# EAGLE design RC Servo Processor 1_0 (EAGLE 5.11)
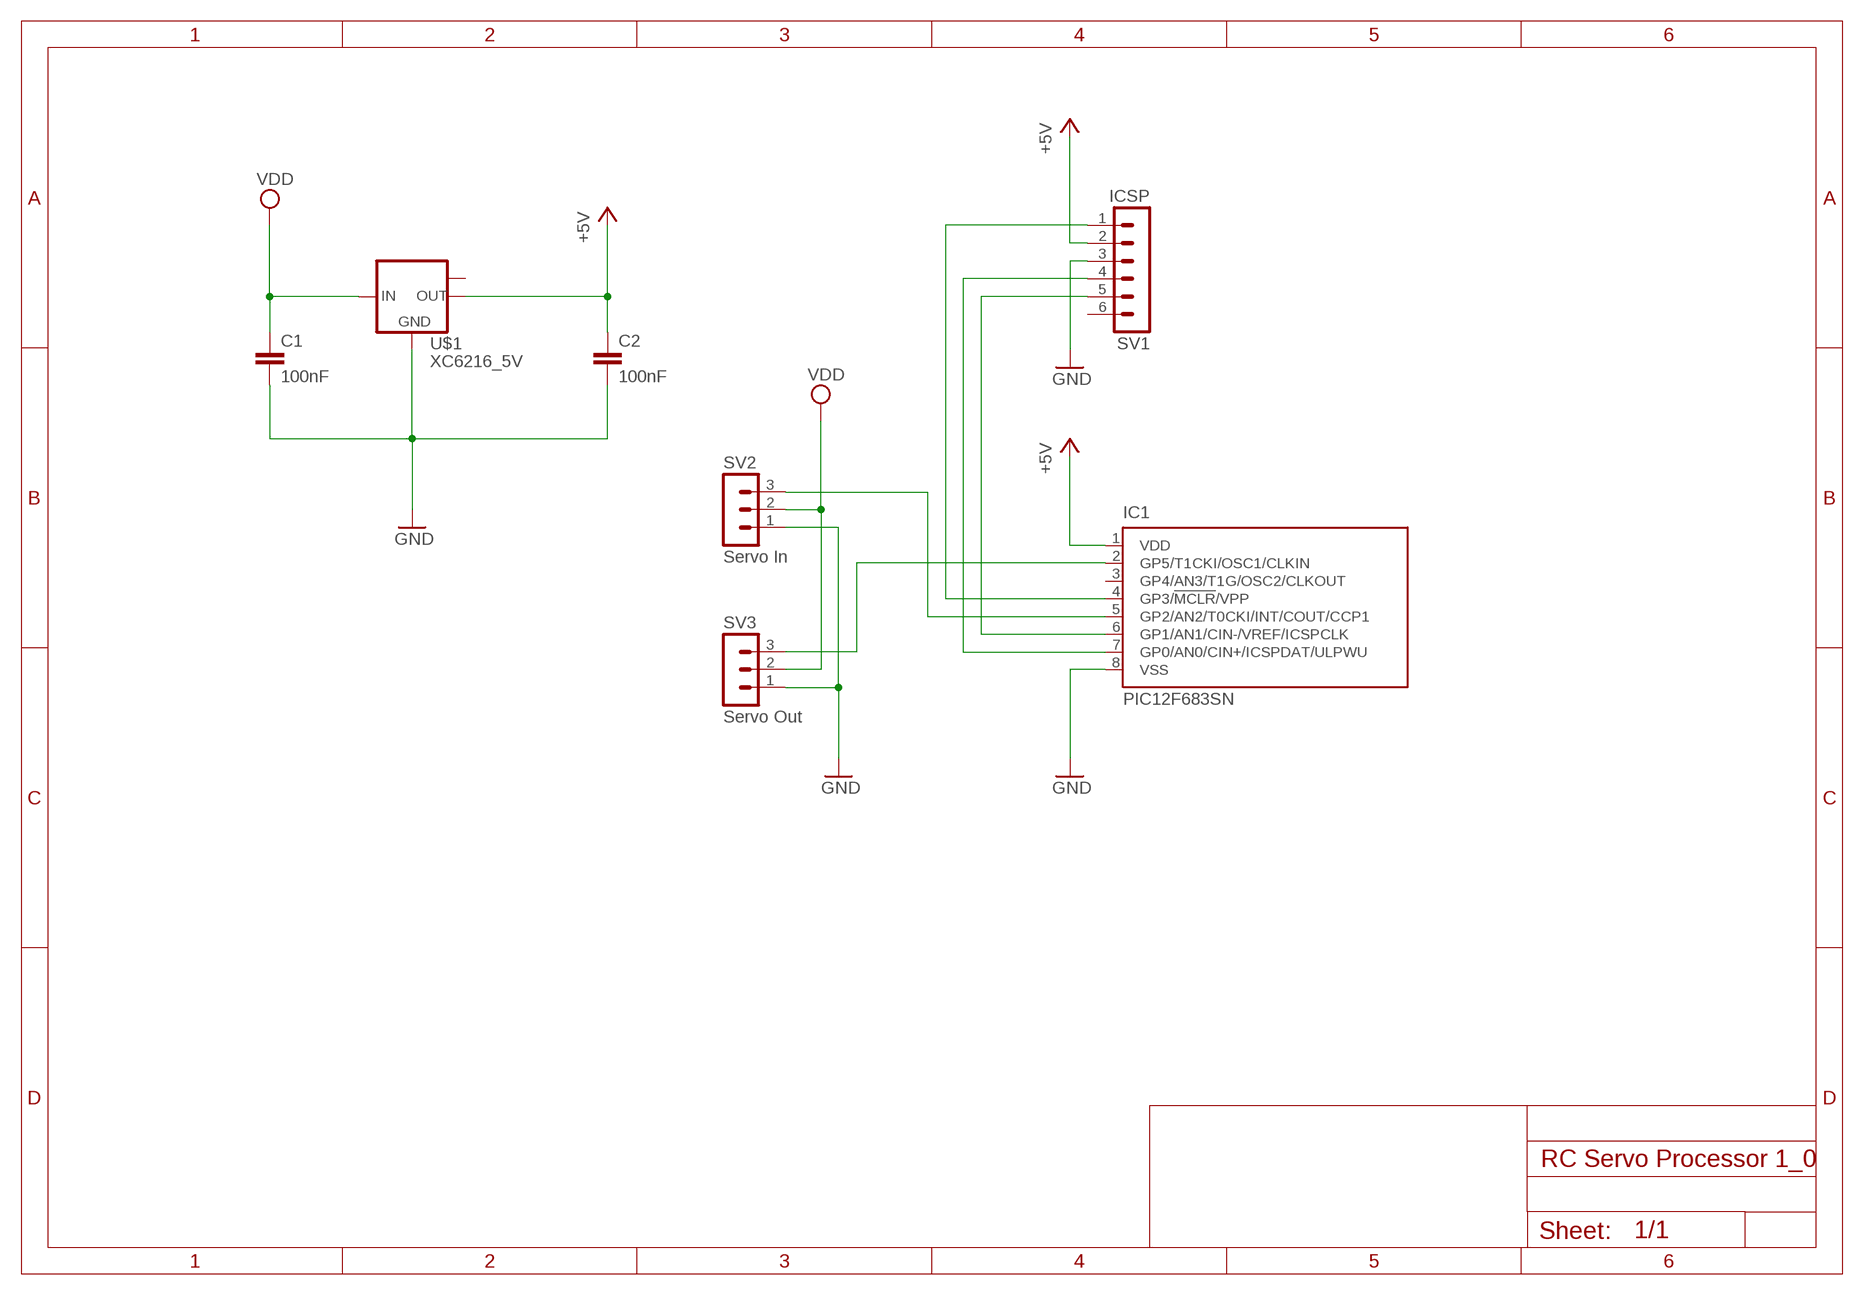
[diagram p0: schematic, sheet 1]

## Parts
C1  100nF  C-EUC0805K  [C0805K]
C2  100nF  C-EUC0805K  [C0805K]
IC1  PIC12F683SN  [SO-08]
SV1  ICSP  MA06-1  [MA06-1]
SV2  Servo In  MA03-1  [MA03-1]
SV3  Servo Out  MA03-1  [MA03-1]
U$1  XC6216_5V  [SOT223]

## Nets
+5V: C2.1 IC1.1(VDD) SV1.2 U$1.1(OUT)
GND: C1.2 C2.2 IC1.8(VSS) SV1.3 SV2.1 SV3.1 U$1.2(GND)
N$1: IC1.4(GP3/!MCLR!/VPP) SV1.1
N$2: IC1.5(GP2/AN2/T0CKI/INT/COUT/CCP1) SV2.3
N$3: IC1.2(GP5/T1CKI/OSC1/CLKIN) SV3.3
N$4: IC1.7(GP0/AN0/CIN+/ICSPDAT/ULPWU) SV1.4
N$5: IC1.6(GP1/AN1/CIN-/VREF/ICSPCLK) SV1.5
VDD: C1.1 SV2.2 SV3.2 U$1.3(IN)
Unconnected: IC1.3(GP4/AN3/T1G/OSC2/CLKOUT) SV1.6 U$1.TAB(OUT1)

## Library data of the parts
C1 C2 = rcl:C-EU: CAPACITOR, European symbol
IC1 = microchip:PIC12F683: 8-Pin Flash-Based, 8-Bit CMOS Microcontrollers with nanoWatt Technology Source: http://ww1.microchip.com/downloads/en/DeviceDoc/41211D_.pdf; MF: MICROCHIP; MPN: PIC12F683-I/SN; OC_FARNELL: 9759042; OC_NEWARK: 61K3434
SV1 = con-lstb:MA06-1: PIN HEADER; OC_FARNELL: unknown; OC_NEWARK: unknown
SV2 SV3 = con-lstb:MA03-1: PIN HEADER; OC_FARNELL: unknown; OC_NEWARK: unknown
U$1 = simonslbr:XC6216_5V: XC6216 LDO 5V Regulator

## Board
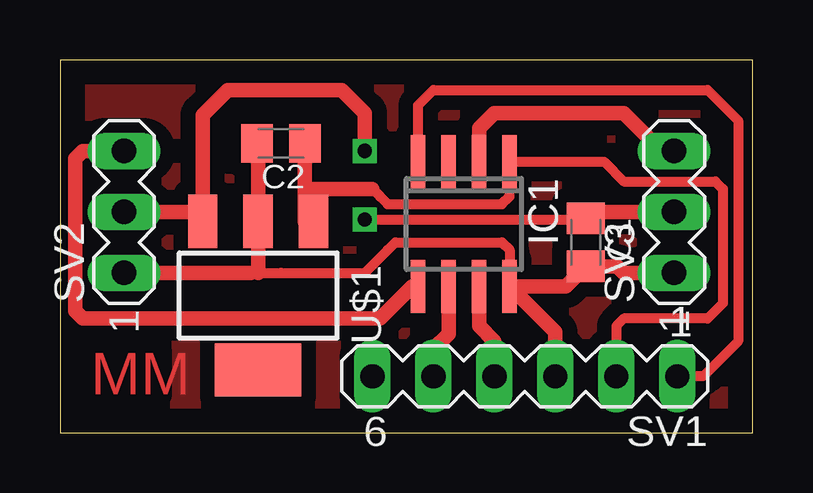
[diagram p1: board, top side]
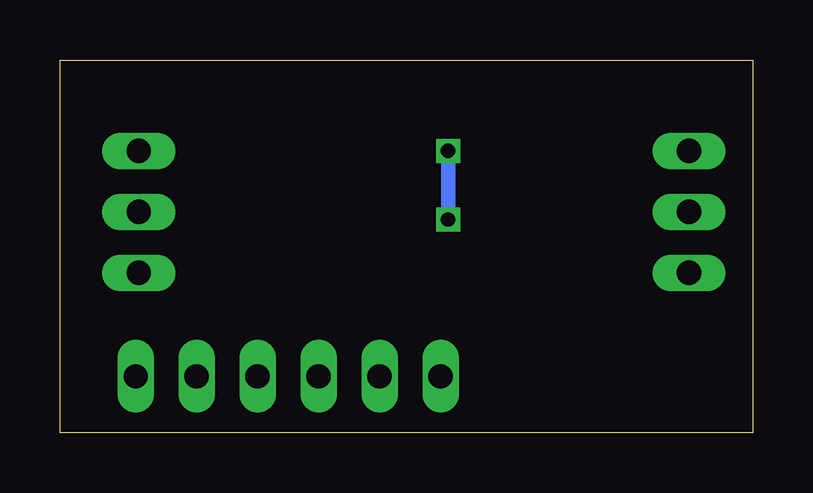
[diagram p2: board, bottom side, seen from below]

Size 28.87 x 15.54 mm. Coordinates in mm from the lower left corner, seen from the top.
Outline: 0,0 28.87,0 28.87,15.54 0,15.54 0,0
Copper layers (1*16): Top 0.035mm / dielectric 1.5mm / Bottom 0.035mm
Design rules "default": minimum track width 10mil, minimum drill 24mil, track to track 8mil, track to pad 8mil, pad to pad 8mil, via to via 8mil, smd to smd 8mil, copper to edge 40mil, drill to drill 8mil, minimum pad ring 10mil, minimum via ring 8mil, stop-mask expansion 4mil, vias tented up to drill 0mil, thermal gap 10mil

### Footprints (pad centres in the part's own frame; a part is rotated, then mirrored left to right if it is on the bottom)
C0805K = smd 1.3 x 1.6: 1 -1,0; 2 1,0
SO-08 = smd 0.6 x 2.2: 1 -1.905,-2.6; 2 -0.635,-2.6; 3 0.635,-2.6; 4 1.905,-2.6; 5 1.905,2.6; 6 0.635,2.6; 7 -0.635,2.6; 8 -1.905,2.6
MA06-1 = drill 1.016 long: 1 -6.35,0; 2 -3.81,0; 3 -1.27,0; 4 1.27,0; 5 3.81,0; 6 6.35,0
MA03-1 = drill 1.016 long: 1 -2.54,0; 2 0,0; 3 2.54,0
SOT223 = smd 1.219 x 2.235: 1 -2.311,-3.099; 2 0,-3.099; 3 2.311,-3.099 | smd 3.6 x 2.2: TAB 0,3.099

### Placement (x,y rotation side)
C1  21.91,7.94 270 top
C2  9.21,12.06 180 top
IC1  16.83,8.7 180 top
SV1  19.37,2.35 180 top
SV2  2.67,9.21 90 top
SV3  25.59,9.21 90 top
U$1  8.26,5.71 180 top

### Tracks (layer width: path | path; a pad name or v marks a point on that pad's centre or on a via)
+5V
  Top 0.406: SV1.2 23.18,4.45 23.5,4.76 26.99,4.76 27.62,5.4 27.62,10.16 27.3,10.48 23.5,10.48 22.67,11.3 IC1.1 18.73,9.84 18.41,9.53 13.65,9.53 13.34,9.84 13.02,10.16
  Top 0.61: C2.1 10.21,8.81 U$1.1 10.57,10.16 13.02,10.16
GND
  Top 0.406: IC1.8 18.73,7.62 18.41,7.94 13.97,7.94 13.65,7.62 12.7,6.67 9.21,6.67 8.26,6.67 7.62,6.67
  Top 0.61: SV2.1 7.62,6.67 7.94,6.67 | SV1.3 20.64,4.19 IC1.8 21.07,6.1 C1.2 23.23,6.94 23.5,6.67 SV3.1 | C2.2 8.26,12.06 U$1.2 8.26,6.67
N$1
  Top 0.406: SV1.1 26.8,2.35 28.26,3.81 28.26,13.02 26.99,14.29 15.56,14.29 14.92,13.65 IC1.4
N$2
  Top 0.61: SV2.3 0.95,11.75 0.64,11.43 0.64,5.08 0.95,4.76 13.34,4.76 14.67,6.1 IC1.5
N$3
  Top 0.61: SV3.3 25.08,11.75 23.5,13.34 18.1,13.34 17.46,12.7 IC1.2
N$4
  Top 0.61: SV1.4 18.1,3.81 17.46,4.45 IC1.7
N$5
  Top 0.61: SV1.5 15.56,3.49 16.19,4.13 IC1.6
N$6
  pour Top (isolate 0.61): 0,15.56 28.89,15.56 28.89,0 0,0
VDD  (via drill 0.6)
  Top 0.406: v12.7,8.89 21.86,8.89 C1.1
  Top 0.61: SV3.2 22.18,9.21 C1.1 | SV2.2 5.94,9.21 U$1.3 5.94,13.25 6.99,14.29 11.75,14.29 12.7,13.34 v12.7,11.75
  Bottom 0.61: v12.7,11.75 v12.7,8.89

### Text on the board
Top: MM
